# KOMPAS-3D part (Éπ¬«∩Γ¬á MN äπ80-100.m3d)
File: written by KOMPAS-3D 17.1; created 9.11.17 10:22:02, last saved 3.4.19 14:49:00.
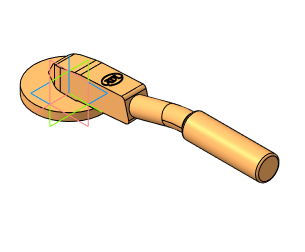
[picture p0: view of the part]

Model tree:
1. Операция без истории:4  (with: Сечение модели:1)

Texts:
  Точка начала. Х
  Точка начала. Y
  Точка начала. Z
